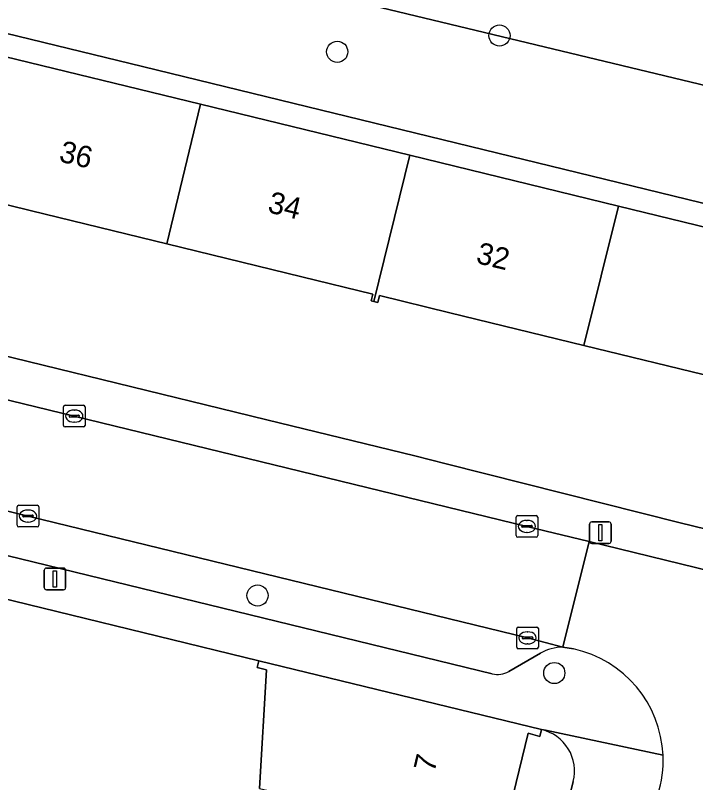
# Model space of a CAD drawing. Extents: x 163266 to 164362, y 381528 to 382286.
# Drawn here: x 164028 to 164059.43, y 382172.66 to 382208.12 of the extents above; entities that cross this region are included whole.
import ezdxf

# ---------------------------------------------------------------- set-up
doc = ezdxf.new("R2010")
doc.units = 0
for name, color, linetype in [('IMGEO_Boom', 7, 'Continuous'), ('IMGEO_Erf', 7, 'Continuous'), ('IMGEO_Groenvoorziening', 7, 'Continuous'), ('IMGEO_Kolk', 7, 'Continuous'), ('IMGEO_Lichtmast', 7, 'Continuous'), ('IMGEO_Loofbos', 7, 'Continuous'), ('IMGEO_Muur', 7, 'Continuous'), ('IMGEO_Pand', 7, 'Continuous'), ('IMGEO_Pand_nummerreeks', 7, 'Continuous'), ('IMGEO_Parkeervlak_open', 7, 'Continuous'), ('IMGEO_Rijbaan_lokaal_open', 7, 'Continuous'), ('IMGEO_Voetpad_open', 7, 'Continuous')]:
    doc.layers.add(name, color=color, linetype=linetype)

msp = doc.modelspace()

# ---------------------------------------------------------------- linework, layer by layer
at = {"layer": 'IMGEO_Boom'}
for centre in [(164050.365, 382207.188), (164042.87, 382206.437), (164039.189, 382181.307), (164052.897, 382177.723)]:
    msp.add_circle(centre, 0.489, dxfattribs=at)
at = {"layer": 'IMGEO_Erf'}
for points in [[(164134.264, 382181.264), (164033.312, 382205.891), (164000, 382214.018), (163852.505, 382250)], [(163933.121, 382229.239), (163944.503, 382226.463), (163955.906, 382223.681), (163965.552, 382221.329), (163975.216, 382218.972), (163984.873, 382216.624), (163994.487, 382214.272), (164000, 382212.927), (164005.87, 382211.495), (164017.273, 382208.714), (164026.918, 382206.362), (164036.553, 382204.012), (164046.218, 382201.655), (164055.863, 382199.302), (164067.246, 382196.526)], [(163935.971, 382214.573), (163946.731, 382211.952), (163957.504, 382209.43), (163958.965, 382209.088), (163965.796, 382207.433), (163967.253, 382207.075), (163976.823, 382204.721), (163978.28, 382204.363), (163985.122, 382202.707), (163997.333, 382199.623), (164008.014, 382197.021), (164009.651, 382196.637), (164018.856, 382194.48), (164020.313, 382194.125), (164027.135, 382192.479), (164028.592, 382192.123), (164038.165, 382189.784), (164039.622, 382189.428), (164046.455, 382187.759), (164047.909, 382187.392), (164058.705, 382184.67), (164069.384, 382182.068)], [(164060.339, 382191.384), (164054.261, 382192.866), (164048.074, 382194.375), (164044.826, 382195.167), (164044.749, 382194.855), (164044.56, 382194.901), (164044.437, 382194.931), (164044.513, 382195.242), (164041.24, 382196.04), (164035.002, 382197.561), (164028.752, 382199.085), (164025.538, 382199.869)], [(164039.275, 382172.395), (164039.608, 382177.876), (164039.171, 382177.983), (164039.249, 382178.295), (164020.573, 382182.844), (164020.506, 382182.524), (164020.069, 382182.631), (164017.879, 382177.606), (164018.818, 382177.357), (164018.108, 382174.473), (164018.543, 382174.366), (164018.466, 382174.055), (164018.029, 382174.164), (164015.811, 382169.146)], [(164052.312, 382175.11), (164052.228, 382174.798), (164051.697, 382174.941), (164050.864, 382171.532)], [(164048.04, 382149.326), (164053.773, 382172.715)]]:
    msp.add_lwpolyline(points, dxfattribs=at)
msp.add_arc((164051.867, 382173.195), 1.966, 345.8571, 76.911, dxfattribs=at)
at = {"layer": 'IMGEO_Groenvoorziening'}
msp.add_lwpolyline([(163823.874, 382261.74), (163832.907, 382259.458), (163872.239, 382250), (164000, 382219.278), (164136.238, 382186.518), (164142.104, 382184.986)], dxfattribs=at)
at = {"layer": 'IMGEO_Kolk'}
for p, q in [((164030.224, 382189.172), (164030.224, 382190.024)), ((164030.299, 382190.098), (164031.151, 382190.098)), ((164031.225, 382190.024), (164031.225, 382189.172)), ((164030.483, 382189.592), (164030.483, 382189.604)), ((164030.921, 382189.555), (164030.523, 382189.555)), ((164030.526, 382189.641), (164030.924, 382189.641)), ((164030.712, 382189.878), (164030.737, 382189.878)), ((164030.967, 382189.604), (164030.967, 382189.592)), ((164030.735, 382189.318), (164030.71, 382189.318)), ((164031.151, 382189.098), (164030.299, 382189.098)), ((164028.084, 382184.554), (164028.084, 382185.406)), ((164028.159, 382185.48), (164029.011, 382185.48)), ((164029.085, 382185.406), (164029.085, 382184.554)), ((164028.343, 382184.974), (164028.343, 382184.986)), ((164028.386, 382185.023), (164028.784, 382185.023)), ((164028.572, 382185.26), (164028.597, 382185.26)), ((164028.827, 382184.986), (164028.827, 382184.974)), ((164051.207, 382185.002), (164052.059, 382185.002)), ((164028.781, 382184.937), (164028.383, 382184.937)), ((164028.595, 382184.7), (164028.57, 382184.7)), ((164051.132, 382184.076), (164051.132, 382184.928)), ((164051.62, 382184.782), (164051.645, 382184.782)), ((164052.133, 382184.928), (164052.133, 382184.076)), ((164029.011, 382184.48), (164028.159, 382184.48)), ((164051.391, 382184.496), (164051.391, 382184.508)), ((164051.829, 382184.459), (164051.431, 382184.459)), ((164051.434, 382184.545), (164051.832, 382184.545)), ((164051.875, 382184.508), (164051.875, 382184.496)), ((164052.059, 382184.002), (164051.207, 382184.002)), ((164051.643, 382184.222), (164051.618, 382184.222)), ((164051.16, 382178.924), (164051.16, 382179.776)), ((164051.235, 382179.85), (164052.087, 382179.85)), ((164051.648, 382179.63), (164051.673, 382179.63)), ((164052.161, 382179.776), (164052.161, 382178.924)), ((164051.419, 382179.344), (164051.419, 382179.356)), ((164051.857, 382179.307), (164051.459, 382179.307)), ((164051.462, 382179.393), (164051.86, 382179.393)), ((164051.903, 382179.356), (164051.903, 382179.344)), ((164051.671, 382179.07), (164051.646, 382179.07)), ((164052.087, 382178.85), (164051.235, 382178.85))]:
    msp.add_line(p, q, dxfattribs=at)
for points in [[(164030.224, 382189.172), (164030.224, 382190.024)], [(164030.299, 382190.098), (164031.151, 382190.098)], [(164031.225, 382190.024), (164031.225, 382189.172)], [(164031.151, 382189.098), (164030.299, 382189.098)], [(164028.084, 382184.554), (164028.084, 382185.406)], [(164028.159, 382185.48), (164029.011, 382185.48)], [(164029.085, 382185.406), (164029.085, 382184.554)], [(164051.207, 382185.002), (164052.059, 382185.002)], [(164051.132, 382184.076), (164051.132, 382184.928)], [(164052.133, 382184.928), (164052.133, 382184.076)], [(164029.011, 382184.48), (164028.159, 382184.48)], [(164052.059, 382184.002), (164051.207, 382184.002)], [(164051.16, 382178.924), (164051.16, 382179.776)], [(164051.235, 382179.85), (164052.087, 382179.85)], [(164052.161, 382179.776), (164052.161, 382178.924)], [(164052.087, 382178.85), (164051.235, 382178.85)]]:
    msp.add_lwpolyline(points, dxfattribs=at)
for centre, radius, start, end in [((164030.301, 382190.022), 0.0765, 91.552, 178.448), ((164030.301, 382190.022), 0.0765, 91.552, 178.448), ((164031.149, 382190.022), 0.0765, 1.552, 88.448), ((164031.149, 382190.022), 0.0765, 1.552, 88.448), ((164030.523, 382189.601), 0.0403, 85.8775, 175.7526), ((164030.52, 382189.591), 0.0366, 178.938, 274.7102), ((164030.924, 382189.598), 0.043, 264.8664, 352.4533), ((164030.928, 382189.603), 0.0386, 1.7309, 96.639), ((164030.301, 382189.174), 0.0765, 181.552, 268.448), ((164030.301, 382189.174), 0.0765, 181.552, 268.448), ((164031.149, 382189.174), 0.0765, 271.552, 358.448), ((164031.149, 382189.174), 0.0765, 271.552, 358.448), ((164028.161, 382185.404), 0.0765, 91.552, 178.448), ((164028.161, 382185.404), 0.0765, 91.552, 178.448), ((164029.009, 382185.404), 0.0765, 1.552, 88.448), ((164029.009, 382185.404), 0.0765, 1.552, 88.448), ((164028.383, 382184.983), 0.0403, 85.8775, 175.7526), ((164028.38, 382184.973), 0.0366, 178.938, 274.7102), ((164028.784, 382184.98), 0.043, 264.8664, 352.4533), ((164028.788, 382184.985), 0.0386, 1.7309, 96.639), ((164051.209, 382184.926), 0.0765, 91.552, 178.448), ((164051.209, 382184.926), 0.0765, 91.552, 178.448), ((164052.057, 382184.926), 0.0765, 1.552, 88.448), ((164052.057, 382184.926), 0.0765, 1.552, 88.448), ((164028.161, 382184.556), 0.0765, 181.552, 268.448), ((164028.161, 382184.556), 0.0765, 181.552, 268.448), ((164029.009, 382184.556), 0.0765, 271.552, 358.448), ((164029.009, 382184.556), 0.0765, 271.552, 358.448), ((164051.431, 382184.505), 0.0403, 85.8775, 175.7526), ((164051.428, 382184.495), 0.0366, 178.938, 274.7102), ((164051.832, 382184.502), 0.043, 264.8664, 352.4533), ((164051.836, 382184.507), 0.0386, 1.7309, 96.639), ((164051.209, 382184.078), 0.0765, 181.552, 268.448), ((164051.209, 382184.078), 0.0765, 181.552, 268.448), ((164052.057, 382184.078), 0.0765, 271.552, 358.448), ((164052.057, 382184.078), 0.0765, 271.552, 358.448), ((164051.237, 382179.774), 0.0765, 91.552, 178.448), ((164051.237, 382179.774), 0.0765, 91.552, 178.448), ((164052.085, 382179.774), 0.0765, 1.552, 88.448), ((164052.085, 382179.774), 0.0765, 1.552, 88.448), ((164051.459, 382179.353), 0.0403, 85.8775, 175.7526), ((164051.456, 382179.343), 0.0366, 178.938, 274.7102), ((164051.86, 382179.35), 0.043, 264.8664, 352.4533), ((164051.864, 382179.355), 0.0386, 1.7309, 96.639), ((164051.237, 382178.926), 0.0765, 181.552, 268.448), ((164051.237, 382178.926), 0.0765, 181.552, 268.448), ((164052.085, 382178.926), 0.0765, 271.552, 358.448), ((164052.085, 382178.926), 0.0765, 271.552, 358.448)]:
    msp.add_arc(centre, radius, start, end, dxfattribs=at)
for centre, major_axis, ratio, start_param, end_param in [((164030.711, 382189.598), (-0.387, 0.002), 0.722429, 4.712389, 7.853982), ((164030.736, 382189.598), (-0.39, 0.002), 0.717154, 1.570796, 4.712389), ((164028.571, 382184.98), (-0.387, 0.002), 0.722429, 4.712389, 7.853982), ((164028.596, 382184.98), (-0.39, 0.002), 0.717154, 1.570796, 4.712389), ((164051.619, 382184.502), (-0.387, 0.002), 0.722429, 4.712389, 7.853982), ((164051.644, 382184.502), (-0.39, 0.002), 0.717154, 1.570796, 4.712389), ((164051.647, 382179.35), (-0.387, 0.002), 0.722429, 4.712389, 7.853982), ((164051.672, 382179.35), (-0.39, 0.002), 0.717154, 1.570796, 4.712389)]:
    msp.add_ellipse(centre, major_axis=major_axis, ratio=ratio, start_param=start_param, end_param=end_param, dxfattribs=at)
at = {"layer": 'IMGEO_Lichtmast'}
for p, q in [((164054.528, 382183.812), (164054.528, 382184.612)), ((164054.528, 382184.612), (164054.528, 382183.812)), ((164054.628, 382184.712), (164055.418, 382184.712)), ((164055.418, 382184.712), (164054.628, 382184.712)), ((164055.518, 382184.612), (164055.518, 382183.812)), ((164055.518, 382183.812), (164055.518, 382184.612)), ((164055.418, 382183.712), (164054.628, 382183.712)), ((164054.628, 382183.712), (164055.418, 382183.712)), ((164029.335, 382181.676), (164029.335, 382182.476)), ((164029.335, 382182.476), (164029.335, 382181.676)), ((164029.435, 382182.576), (164030.225, 382182.576)), ((164030.225, 382182.576), (164029.435, 382182.576)), ((164030.325, 382182.476), (164030.325, 382181.676)), ((164030.325, 382181.676), (164030.325, 382182.476)), ((164030.225, 382181.576), (164029.435, 382181.576)), ((164029.435, 382181.576), (164030.225, 382181.576))]:
    msp.add_line(p, q, dxfattribs=at)
for points in [[(164054.948, 382184.587), (164055.098, 382184.587), (164055.098, 382183.837), (164054.948, 382183.837), (164054.948, 382184.587)], [(164029.755, 382182.451), (164029.905, 382182.451), (164029.905, 382181.701), (164029.755, 382181.701), (164029.755, 382182.451)]]:
    msp.add_lwpolyline(points, dxfattribs=at)
for centre, start, end in [((164054.628, 382184.612), 90, 180), ((164054.628, 382184.612), 90, 180), ((164055.418, 382184.612), 0, 90), ((164055.418, 382184.612), 360, 90), ((164054.628, 382183.812), 180, 270), ((164054.628, 382183.812), 180, 270), ((164055.418, 382183.812), 270, 0), ((164055.418, 382183.812), 270, 0), ((164029.435, 382182.476), 90, 180), ((164029.435, 382182.476), 90, 180), ((164030.225, 382182.476), 0, 90), ((164030.225, 382182.476), 360, 90), ((164029.435, 382181.676), 180, 270), ((164029.435, 382181.676), 180, 270), ((164030.225, 382181.676), 270, 0), ((164030.225, 382181.676), 270, 0)]:
    msp.add_arc(centre, 0.1, start, end, dxfattribs=at)
at = {"layer": 'IMGEO_Loofbos'}
for points in [[(164142.104, 382184.986), (164136.238, 382186.518), (164000, 382219.278), (163872.239, 382250), (163832.907, 382259.458), (163823.874, 382261.74)], [(163817.409, 382251.574), (163819.3, 382251.045), (163819.962, 382253.749), (163820.909, 382257.71), (163830.652, 382255.331), (163852.505, 382250), (164000, 382214.018), (164033.312, 382205.891), (164134.264, 382181.264), (164140.582, 382179.712)]]:
    msp.add_lwpolyline(points, dxfattribs=at)
at = {"layer": 'IMGEO_Muur'}
for points in [[(164028.592, 382192.123), (164038.165, 382189.784)], [(164047.909, 382187.392), (164058.705, 382184.67)], [(164039.249, 382178.295), (164020.573, 382182.844)]]:
    msp.add_lwpolyline(points, dxfattribs=at)
at = {"layer": 'IMGEO_Pand'}
for points in [[(164035.002, 382197.561), (164036.553, 382204.012), (164026.918, 382206.362), (164025.282, 382199.601), (164025.461, 382199.557), (164025.538, 382199.869), (164028.752, 382199.085)], [(164035.002, 382197.561), (164041.24, 382196.04), (164044.513, 382195.242), (164044.437, 382194.931), (164044.56, 382194.901), (164046.218, 382201.655), (164036.553, 382204.012)], [(164055.863, 382199.302), (164046.218, 382201.655), (164044.56, 382194.901), (164044.749, 382194.855), (164044.826, 382195.167), (164048.074, 382194.375), (164054.261, 382192.866)], [(164055.863, 382199.302), (164054.261, 382192.866), (164060.339, 382191.384), (164059.939, 382189.741), (164065.011, 382188.487), (164064.929, 382188.116), (164065.158, 382188.061), (164067.246, 382196.526)], [(164039.382, 382169.304), (164039.345, 382169.148), (164046.759, 382167.367), (164046.797, 382167.522), (164047.5, 382170.401), (164049.19, 382169.987), (164049.641, 382171.832), (164050.864, 382171.532), (164051.697, 382174.941), (164052.228, 382174.798), (164052.312, 382175.11), (164039.249, 382178.295), (164039.171, 382177.983), (164039.608, 382177.876), (164039.275, 382172.395), (164040.078, 382172.202)]]:
    msp.add_lwpolyline(points, close=True, dxfattribs=at)
at = {"layer": 'IMGEO_Parkeervlak_open'}
for points in [[(164053.294, 382178.917), (164051.662, 382179.351), (164028.586, 382184.982), (164010.818, 382189.298), (164007.933, 382190.004), (164007.259, 382190.162)], [(164009.899, 382187.477), (164028.244, 382182.998), (164050.035, 382177.688)], [(164050.798, 382177.79), (164052.264, 382178.644)]]:
    msp.add_lwpolyline(points, dxfattribs=at)
for centre, radius, start, end in [((164053.276, 382176.904), 2.013, 89.4962, 120.1935), ((164050.273, 382178.809), 1.146, 257.9965, 297.2321)]:
    msp.add_arc(centre, radius, start, end, dxfattribs=at)
at = {"layer": 'IMGEO_Rijbaan_lokaal_open'}
msp.add_lwpolyline([(164053.294, 382178.917), (164054.512, 382183.806), (164051.633, 382184.501), (164030.724, 382189.597), (164010.84, 382194.429), (164009.119, 382194.852), (164007.933, 382190.004), (164010.818, 382189.298), (164028.586, 382184.982), (164051.662, 382179.351)], close=True, dxfattribs=at)
msp.add_lwpolyline([(164071.318, 382179.688), (164054.512, 382183.806), (164053.294, 382178.917), (164053.79, 382178.837)], dxfattribs=at)
for centre, radius, start, end in [((164052.671, 382173.704), 5.253, 2.3775, 77.7021), ((164052.669, 382173.703), 5.256, 342.3446, 2.3875)]:
    msp.add_arc(centre, radius, start, end, dxfattribs=at)
at = {"layer": 'IMGEO_Voetpad_open'}
for points in [[(163932.888, 382213.459), (163947.637, 382209.835), (163951.868, 382208.832), (163970.464, 382204.278), (163992.893, 382198.806), (163993.571, 382198.644), (164000, 382197.076), (164009.119, 382194.852), (164010.84, 382194.429), (164030.724, 382189.597), (164051.633, 382184.501), (164054.512, 382183.806), (164071.318, 382179.688), (164074.461, 382178.912), (164093.411, 382174.302), (164114.312, 382169.171), (164121.017, 382167.561), (164121.171, 382168.134)], [(164120.079, 382169.717), (164107.813, 382172.789), (164100.999, 382174.463), (164099.541, 382174.816), (164089.97, 382177.138), (164088.512, 382177.491), (164081.698, 382179.165), (164080.238, 382179.509), (164069.384, 382182.068), (164058.705, 382184.67), (164047.909, 382187.392), (164046.455, 382187.759), (164039.622, 382189.428), (164038.165, 382189.784), (164028.592, 382192.123), (164027.135, 382192.479), (164020.313, 382194.125), (164018.856, 382194.48), (164009.651, 382196.637), (164008.014, 382197.021), (163997.333, 382199.623)], [(164002.013, 382187.71), (164007.521, 382186.025), (164020.573, 382182.844), (164039.249, 382178.295), (164052.312, 382175.11), (164052.486, 382175.086), (164057.92, 382173.922)], [(164028.244, 382182.998), (164009.899, 382187.477)], [(164050.035, 382177.688), (164028.244, 382182.998)], [(164053.79, 382178.837), (164053.294, 382178.917)], [(164052.264, 382178.644), (164050.798, 382177.79)], [(164057.92, 382173.922), (164052.486, 382175.086), (164052.312, 382175.11)], [(164053.773, 382172.715), (164048.04, 382149.326), (164049.998, 382148.86), (164048.546, 382142.852), (164046.57, 382143.324), (164042.999, 382128.602), (164036.608, 382102.251), (164036.138, 382100.312), (164031.812, 382082.475), (164031.336, 382080.636), (164030.394, 382076.626)]]:
    msp.add_lwpolyline(points, dxfattribs=at)
for centre, radius, start, end in [((164053.276, 382176.904), 2.013, 89.4962, 120.1935), ((164052.671, 382173.704), 5.253, 2.3775, 77.7021), ((164050.273, 382178.809), 1.146, 257.9965, 297.2321), ((164051.867, 382173.195), 1.966, 345.8571, 76.911), ((164052.669, 382173.703), 5.256, 342.3446, 2.3875)]:
    msp.add_arc(centre, radius, start, end, dxfattribs=at)

# ---------------------------------------------------------------- texts
at = {"layer": 'IMGEO_Pand_nummerreeks'}
for s, rotation, p in [('36', 346.296, (164029.974, 382201.381)), ('34', 346.296, (164039.613, 382199.031)), ('32', 346.3028, (164049.239, 382196.685)), ('7', 76.2637, (164047.356, 382173.095))]:
    msp.add_text(s, height=1, rotation=rotation, dxfattribs=at).set_placement(p)

doc.saveas('drawing.dxf')
